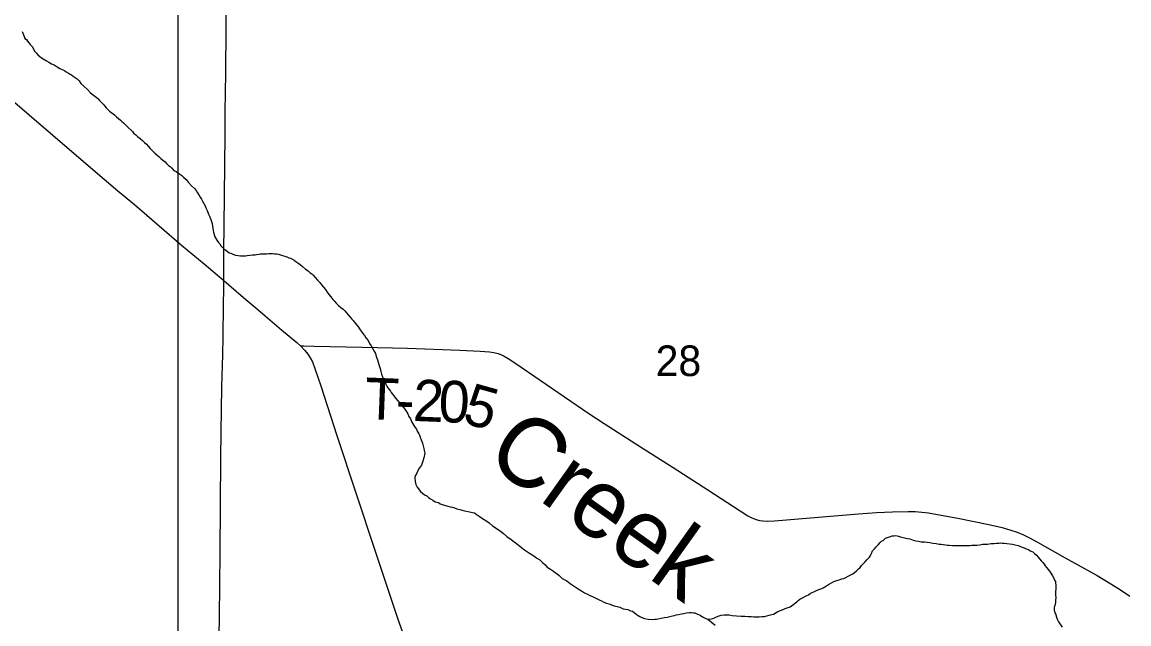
# Model space of a CAD drawing. Extents: x 0 to 68, y 0 to 52.9.
# Drawn here: x 58.195 to 62.186, y 47.686 to 49.856 of the extents above; entities that cross this region are included whole.
import ezdxf

# ---------------------------------------------------------------- set-up
doc = ezdxf.new("R2010")
doc.units = 0
for name, color, linetype in [('Default', 7, 'Continuous'), ('GM_X_County_Road', 7, 'Continuous'), ('GM_X_Minor_River', 7, 'Continuous'), ('GM_X_Minor_River_Text', 7, 'Continuous'), ('GM_X_State_Route', 7, 'Continuous'), ('GM_X_Township_Road', 7, 'Continuous'), ('GM_X_Township_Road_Text', 7, 'Continuous')]:
    doc.layers.add(name, color=color, linetype=linetype)

msp = doc.modelspace()

# ---------------------------------------------------------------- linework, layer by layer
at = {"layer": 'Default'}
msp.add_line((58.7572, 34.4614), (58.7572, 52.9414), dxfattribs=at)
at = {"layer": 'GM_X_County_Road'}
for points in [[(58.9224, 48.9239), (58.9222, 49.0317), (58.9231, 49.1219), (58.9266, 49.4499), (58.9266, 49.5319), (58.9295, 49.6713), (58.9323, 49.9911)], [(58.8822, 45.4806), (58.8824, 45.5626), (58.8841, 45.7103), (58.8853, 45.8252), (58.8903, 46.2849), (58.8915, 46.408), (58.8932, 46.5305), (58.8951, 46.7109), (58.8974, 47.0064), (58.9001, 47.2526), (58.9023, 47.4412), (58.907, 47.7121), (58.9091, 47.9419), (58.9114, 48.2867), (58.9124, 48.3769), (58.9148, 48.5411), (58.918, 48.656), (58.9192, 48.7216), (58.9206, 48.8365), (58.9218, 48.8938), (58.9224, 48.9239)]]:
    msp.add_lwpolyline(points, dxfattribs=at)
at = {"layer": 'GM_X_Minor_River'}
for points in [[(58.1947, 49.8217), (58.1977, 49.8156), (58.1996, 49.8096), (58.2015, 49.8035), (58.2045, 49.7965), (58.2105, 49.7934), (58.2144, 49.7873), (58.2233, 49.7751), (58.2323, 49.767), (58.2352, 49.7589), (58.2401, 49.7498), (58.2451, 49.7457), (58.2511, 49.7376), (58.258, 49.7315), (58.265, 49.7274), (58.271, 49.7233), (58.277, 49.7202), (58.283, 49.7161), (58.291, 49.7109), (58.301, 49.7058), (58.31, 49.7017), (58.318, 49.6975), (58.331, 49.6883), (58.342, 49.6842), (58.348, 49.6811), (58.354, 49.677), (58.362, 49.6718), (58.368, 49.6687), (58.373, 49.6657), (58.379, 49.6616), (58.386, 49.6565), (58.393, 49.6513), (58.3999, 49.6442), (58.4069, 49.6351), (58.4178, 49.6249), (58.4308, 49.6127), (58.4417, 49.6015), (58.4527, 49.5923), (58.4616, 49.5851), (58.4676, 49.58), (58.4736, 49.5729), (58.4815, 49.5658), (58.4895, 49.5577), (58.4984, 49.5465)], [(58.4984, 49.5465), (58.5104, 49.5353), (58.5273, 49.522), (58.5353, 49.5149), (58.5423, 49.5088), (58.5492, 49.5026), (58.5542, 49.4976), (58.5602, 49.4924), (58.5661, 49.4863), (58.5721, 49.4802), (58.593, 49.4619), (58.598, 49.4548), (58.605, 49.4497), (58.6109, 49.4436), (58.6199, 49.4364), (58.6289, 49.4293), (58.6358, 49.4221), (58.6428, 49.416), (58.6498, 49.4089), (58.6567, 49.3998), (58.6656, 49.3906), (58.6736, 49.3835), (58.6806, 49.3774), (58.6886, 49.3702), (58.6955, 49.3641), (58.7005, 49.359), (58.7055, 49.3559), (58.7105, 49.3519), (58.7154, 49.3458), (58.7224, 49.3386), (58.7284, 49.3356), (58.7334, 49.3305), (58.7413, 49.3213), (58.7503, 49.3172), (58.7553, 49.3141), (58.7633, 49.308), (58.7703, 49.3029), (58.7773, 49.2967), (58.7862, 49.2886), (58.7951, 49.2774), (58.8061, 49.2652), (58.816, 49.2561), (58.822, 49.2489), (58.8269, 49.2408), (58.8319, 49.2337), (58.8368, 49.2246), (58.8417, 49.2175), (58.8447, 49.2105), (58.8496, 49.2014), (58.8545, 49.1933), (58.8574, 49.1862), (58.8623, 49.1761), (58.8672, 49.164), (58.8721, 49.1539), (58.876, 49.1408), (58.8799, 49.1297), (58.8818, 49.1196), (58.8855, 49.0984), (58.8875, 49.0904), (58.8894, 49.0823), (58.8933, 49.0762), (58.8973, 49.0702), (58.9032, 49.061), (58.9072, 49.056), (58.9121, 49.0479), (58.9221, 49.0387), (58.929, 49.0336), (58.934, 49.0305), (58.942, 49.0244), (58.948, 49.0223), (58.955, 49.0192), (58.9641, 49.016), (58.9741, 49.0139), (58.9821, 49.0128), (58.9892, 49.0127), (58.9942, 49.0136), (59.0003, 49.0136), (59.0063, 49.0145), (59.0154, 49.0154), (59.0255, 49.0173), (59.0346, 49.0171), (59.0396, 49.0181), (59.0487, 49.019), (59.0537, 49.0199), (59.0618, 49.0208), (59.0699, 49.0207), (59.0759, 49.0206), (59.084, 49.0215), (59.092, 49.0214), (59.0981, 49.0213), (59.1051, 49.0202), (59.1132, 49.0201), (59.1192, 49.019), (59.1342, 49.0148), (59.1423, 49.0117), (59.1493, 49.0096), (59.1563, 49.0065), (59.1623, 49.0044), (59.1673, 49.0023), (59.1753, 48.9972), (59.1813, 48.9931)], [(59.1813, 48.9931), (59.1893, 48.988), (59.1973, 48.9819), (59.2062, 48.9747), (59.2162, 48.9655), (59.2262, 48.9594), (59.2332, 48.9522), (59.2391, 48.9482), (59.2441, 48.9431), (59.2511, 48.9349), (59.26, 48.9258), (59.268, 48.9166), (59.2749, 48.9085), (59.2819, 48.9004), (59.2888, 48.8913), (59.2947, 48.8821), (59.3007, 48.874), (59.3076, 48.8649), (59.3155, 48.8557), (59.3215, 48.8496), (59.3274, 48.8425), (59.3354, 48.8344), (59.3444, 48.8272), (59.3524, 48.8211), (59.3583, 48.815), (59.3643, 48.8079), (59.3702, 48.8008), (59.3782, 48.7926), (59.3841, 48.7855), (59.3901, 48.7784), (59.396, 48.7703), (59.403, 48.7622), (59.4079, 48.7561), (59.4119, 48.75), (59.4178, 48.7419), (59.4238, 48.7338), (59.4297, 48.7257), (59.4346, 48.7176), (59.4426, 48.7074), (59.4475, 48.6973), (59.4534, 48.6882), (59.4652, 48.6669), (59.4692, 48.6609), (59.4721, 48.6508), (59.4759, 48.6377), (59.4808, 48.6215), (59.4856, 48.6074), (59.4885, 48.5963), (59.4914, 48.5872), (59.4943, 48.5772), (59.4972, 48.5701), (59.5002, 48.564), (59.5031, 48.559), (59.5061, 48.5509), (59.51, 48.5438), (59.514, 48.5377), (59.5189, 48.5316), (59.5229, 48.5256), (59.5258, 48.5205), (59.5308, 48.5144), (59.5347, 48.5093), (59.5427, 48.4992), (59.5496, 48.4901), (59.5566, 48.4819), (59.5645, 48.4728), (59.5714, 48.4647), (59.5774, 48.4565), (59.5823, 48.4494), (59.5863, 48.4434), (59.5892, 48.4343), (59.5951, 48.4252), (59.6, 48.4141), (59.6069, 48.4019), (59.6128, 48.3938), (59.6168, 48.3887), (59.6188, 48.3837), (59.6217, 48.3776), (59.6257, 48.3715), (59.6276, 48.3665), (59.6305, 48.3594), (59.6335, 48.3503), (59.6383, 48.3382), (59.6412, 48.3281), (59.6431, 48.3191), (59.645, 48.312), (59.6469, 48.3019), (59.6437, 48.2849), (59.6395, 48.2729), (59.6353, 48.2589), (59.6281, 48.2489), (59.6241, 48.244), (59.6178, 48.23), (59.6127, 48.22), (59.6106, 48.214), (59.6124, 48.1999), (59.6143, 48.1889), (59.6192, 48.1787), (59.6311, 48.1635), (59.646, 48.1513), (59.6541, 48.1482), (59.662, 48.141)], [(59.662, 48.141), (59.668, 48.1369), (59.676, 48.1328), (59.684, 48.1267), (59.6961, 48.1235), (59.703, 48.1194), (59.7101, 48.1163), (59.7301, 48.111), (59.7382, 48.1089), (59.7472, 48.1068), (59.7542, 48.1047), (59.7622, 48.1015), (59.7733, 48.0984), (59.7903, 48.0941), (59.8034, 48.0909), (59.8185, 48.0877), (59.8265, 48.0866), (59.8325, 48.0815), (59.8435, 48.0744), (59.8555, 48.0662), (59.8675, 48.059), (59.8794, 48.0508), (59.8914, 48.0396), (59.9084, 48.0293), (59.9204, 48.0211), (59.9313, 48.0119), (59.9433, 48.0017), (59.9582, 47.9905), (59.9732, 47.9792), (59.9892, 47.967), (60.0061, 47.9537), (60.0251, 47.9414), (60.0401, 47.9311), (60.051, 47.923), (60.062, 47.9168), (60.071, 47.9076), (60.08, 47.9005), (60.0889, 47.8913), (60.0999, 47.8831), (60.1109, 47.876), (60.1189, 47.8708), (60.1239, 47.8668), (60.1318, 47.8606), (60.1428, 47.8494), (60.1588, 47.8412), (60.1718, 47.832), (60.1857, 47.8218), (60.1997, 47.8125), (60.2127, 47.8053), (60.2227, 47.7982), (60.2337, 47.794), (60.2427, 47.7889), (60.2517, 47.7847), (60.2788, 47.7723), (60.2838, 47.7692), (60.2928, 47.7651), (60.3028, 47.761), (60.3108, 47.7588), (60.3158, 47.7568), (60.3228, 47.7537), (60.3299, 47.7516), (60.3349, 47.7505), (60.3409, 47.7494), (60.3499, 47.7463), (60.362, 47.7411), (60.379, 47.7379), (60.3891, 47.7337), (60.3961, 47.7316), (60.4021, 47.7275), (60.409, 47.7214), (60.417, 47.7163), (60.423, 47.7132), (60.43, 47.7091), (60.4391, 47.7059), (60.4521, 47.7038), (60.4672, 47.7025), (60.4763, 47.7034), (60.4823, 47.7034), (60.4884, 47.7043), (60.4995, 47.7071), (60.5116, 47.709), (60.5217, 47.7109), (60.5308, 47.7128), (60.5409, 47.7156), (60.548, 47.7166), (60.553, 47.7185), (60.5621, 47.7204), (60.5732, 47.7223), (60.5813, 47.7242), (60.5914, 47.726), (60.6015, 47.7269), (60.6085, 47.7268), (60.6156, 47.7267), (60.6206, 47.7256), (60.6276, 47.7225), (60.6396, 47.7174), (60.6486, 47.7122), (60.6556, 47.7081), (60.6606, 47.706), (60.6676, 47.7029), (60.6727, 47.7029)], [(60.6727, 47.7029), (60.6807, 47.7048), (60.6858, 47.7057), (60.6919, 47.7086), (60.699, 47.7116), (60.7081, 47.7155), (60.7161, 47.7174), (60.7273, 47.7192), (60.7373, 47.7191), (60.7444, 47.719), (60.7554, 47.7169), (60.7715, 47.7156), (60.7886, 47.7144), (60.8017, 47.7142), (60.8128, 47.7131), (60.8239, 47.7129), (60.8339, 47.7118), (60.844, 47.7117), (60.853, 47.7116), (60.8621, 47.7124), (60.8722, 47.7133), (60.8803, 47.7152), (60.8894, 47.7181), (60.8985, 47.72), (60.9045, 47.7219), (60.9106, 47.7249), (60.9208, 47.7308), (60.9299, 47.7347), (60.939, 47.7386), (60.9471, 47.7415), (60.9572, 47.7453), (60.9643, 47.7483), (60.9694, 47.7512), (60.9785, 47.7571), (60.9836, 47.7621), (60.9887, 47.766), (60.9938, 47.771), (60.9999, 47.7749), (61.0049, 47.7779), (61.0252, 47.7887), (61.0303, 47.7916), (61.0384, 47.7965), (61.0496, 47.8024), (61.0617, 47.8073), (61.0718, 47.8111), (61.0789, 47.8141), (61.084, 47.816), (61.0901, 47.8199), (61.0962, 47.8239), (61.1033, 47.8288), (61.1134, 47.8347), (61.1225, 47.8386), (61.1326, 47.8425), (61.1417, 47.8454), (61.1508, 47.8483), (61.1589, 47.8502), (61.166, 47.8541), (61.1741, 47.858), (61.1833, 47.8629), (61.1904, 47.8669), (61.1954, 47.8708), (61.2056, 47.8787), (61.2117, 47.8846), (61.2168, 47.8896), (61.2219, 47.8966), (61.2291, 47.9035), (61.2352, 47.9095), (61.2413, 47.9174), (61.2464, 47.9224), (61.2505, 47.9273), (61.2546, 47.9333), (61.2578, 47.9403), (61.2619, 47.9493), (61.269, 47.9572), (61.2752, 47.9642), (61.2823, 47.9711), (61.2895, 47.9801), (61.2946, 47.984), (61.2996, 47.987), (61.3088, 47.9949), (61.327, 48.0017), (61.3321, 48.0036), (61.3381, 48.0035), (61.3442, 48.0045), (61.3502, 48.0034), (61.3552, 48.0023), (61.3622, 48.0002), (61.3723, 47.9981), (61.3823, 47.9959), (61.3893, 47.9938), (61.3964, 47.9927), (61.4024, 47.9906), (61.4084, 47.9886), (61.4174, 47.9854), (61.4275, 47.9843), (61.4375, 47.9821), (61.4496, 47.982), (61.4587, 47.9809), (61.4687, 47.9797), (61.4788, 47.9776), (61.4908, 47.9764)], [(61.4908, 47.9764), (61.5019, 47.9743), (61.5089, 47.9732), (61.516, 47.9721), (61.525, 47.9709), (61.532, 47.9699), (61.5381, 47.9698), (61.5502, 47.9686), (61.5622, 47.9685), (61.5723, 47.9683), (61.5834, 47.9692), (61.5945, 47.969), (61.6045, 47.9689), (61.6126, 47.9688), (61.6197, 47.9697), (61.6267, 47.9706), (61.6378, 47.9705), (61.6489, 47.9713), (61.659, 47.9732), (61.6761, 47.974), (61.6892, 47.9758), (61.7003, 47.9767), (61.7094, 47.9776), (61.7174, 47.9775), (61.7235, 47.9784), (61.7295, 47.9773), (61.7366, 47.9772), (61.7466, 47.9761), (61.7667, 47.9738), (61.7758, 47.9717), (61.7868, 47.9685), (61.7958, 47.9654), (61.8019, 47.9633), (61.8089, 47.9602), (61.8159, 47.9571), (61.8239, 47.954), (61.8309, 47.9499), (61.8399, 47.9457), (61.8459, 47.9396), (61.8529, 47.9345), (61.8588, 47.9274), (61.8638, 47.9203), (61.8707, 47.9122), (61.8757, 47.9071), (61.8806, 47.901), (61.8846, 47.8959), (61.8896, 47.8898), (61.8965, 47.8817), (61.9024, 47.8726), (61.9103, 47.8594), (61.9153, 47.8513), (61.9182, 47.8443), (61.9212, 47.8392), (61.9221, 47.8331), (61.923, 47.8271), (61.9229, 47.8211), (61.9228, 47.813), (61.9217, 47.802), (61.9215, 47.79), (61.9224, 47.7809), (61.9223, 47.7709), (61.9212, 47.7639), (61.9191, 47.7528), (61.917, 47.7458), (61.9168, 47.7368), (61.9197, 47.7267), (61.9227, 47.7196), (61.9246, 47.7136), (61.9265, 47.7065), (61.9285, 47.7005), (61.9324, 47.6934), (61.9463, 47.6741)], [(60.6676, 47.7029), (60.6945, 47.6815)]]:
    msp.add_lwpolyline(points, dxfattribs=at)
at = {"layer": 'GM_X_State_Route'}
for points in [[(57.6839, 49.9805), (57.7114, 49.9553), (57.7739, 49.9022), (57.8357, 49.8485), (57.9486, 49.7534), (58.048, 49.6678), (58.3908, 49.375), (58.4906, 49.2899), (58.5404, 49.2473), (58.5999, 49.1988), (58.769, 49.0515), (58.8509, 48.9849), (58.9224, 48.9239), (58.9405, 48.9085)], [(58.9405, 48.9085), (59.0015, 48.8564), (59.0453, 48.8193), (59.0714, 48.7965), (59.1297, 48.7468), (59.1849, 48.7012), (59.1982, 48.6891), (59.2146, 48.6724), (59.2249, 48.6593), (59.234, 48.6453), (59.2414, 48.6305), (59.2505, 48.6074), (59.2716, 48.5451), (59.3303, 48.3656), (59.4672, 47.9526), (59.5496, 47.7032), (59.5663, 47.657)]]:
    msp.add_lwpolyline(points, dxfattribs=at)
at = {"layer": 'GM_X_Township_Road'}
msp.add_lwpolyline([(59.1982, 48.6891), (59.2111, 48.6886), (59.2485, 48.6871), (59.4209, 48.6845), (59.5849, 48.6798), (59.7734, 48.6726), (59.8472, 48.6696), (59.8798, 48.6672), (59.8957, 48.6648), (59.9113, 48.6608), (59.9263, 48.6549), (59.9335, 48.6513), (59.9477, 48.6433), (59.9752, 48.6255), (60.1509, 48.5045), (60.239, 48.4443), (60.2942, 48.4087), (60.4254, 48.3245), (60.5432, 48.2498), (60.6675, 48.17), (60.784, 48.0934), (60.812, 48.0758), (60.8268, 48.0682), (60.8423, 48.0622), (60.8537, 48.0595), (60.8667, 48.0574), (60.8833, 48.0565), (60.9082, 48.0575), (61.0963, 48.0732), (61.2108, 48.0833), (61.2761, 48.0883), (61.3335, 48.0907), (61.3908, 48.0915), (61.4153, 48.0909), (61.4397, 48.0892), (61.4641, 48.0864), (61.4964, 48.0812), (61.5689, 48.0677), (61.6814, 48.0447), (61.7292, 48.0332), (61.7607, 48.0243), (61.7839, 48.0165), (61.8064, 48.0071), (61.8285, 47.9964), (61.8573, 47.9809), (61.9571, 47.9241), (62.0718, 47.8602), (62.1212, 47.8311), (62.1558, 47.8092), (62.1895, 47.786)], dxfattribs=at)

# ---------------------------------------------------------------- texts
at = {"layer": 'Default'}
msp.add_text('28', height=0.1105, rotation=0, dxfattribs=at).set_placement((60.4795, 48.5797))
at = {"layer": 'GM_X_Minor_River_Text'}
msp.add_text('Creek', height=0.2501, rotation=324.5413, dxfattribs=at).set_placement((59.8575, 48.275))
at = {"layer": 'GM_X_Township_Road_Text'}
for s, rotation, p in [('T', 357.758, (59.4286, 48.425)), ('2', 357.7647, (59.6022, 48.4182)), ('0', 357.7802, (59.6946, 48.4145)), ('5', 344.4049, (59.7778, 48.4124)), ('-', 357.7621, (59.5407, 48.4206))]:
    msp.add_text(s, height=0.15, rotation=rotation, dxfattribs=at).set_placement(p)

doc.saveas('drawing.dxf')
